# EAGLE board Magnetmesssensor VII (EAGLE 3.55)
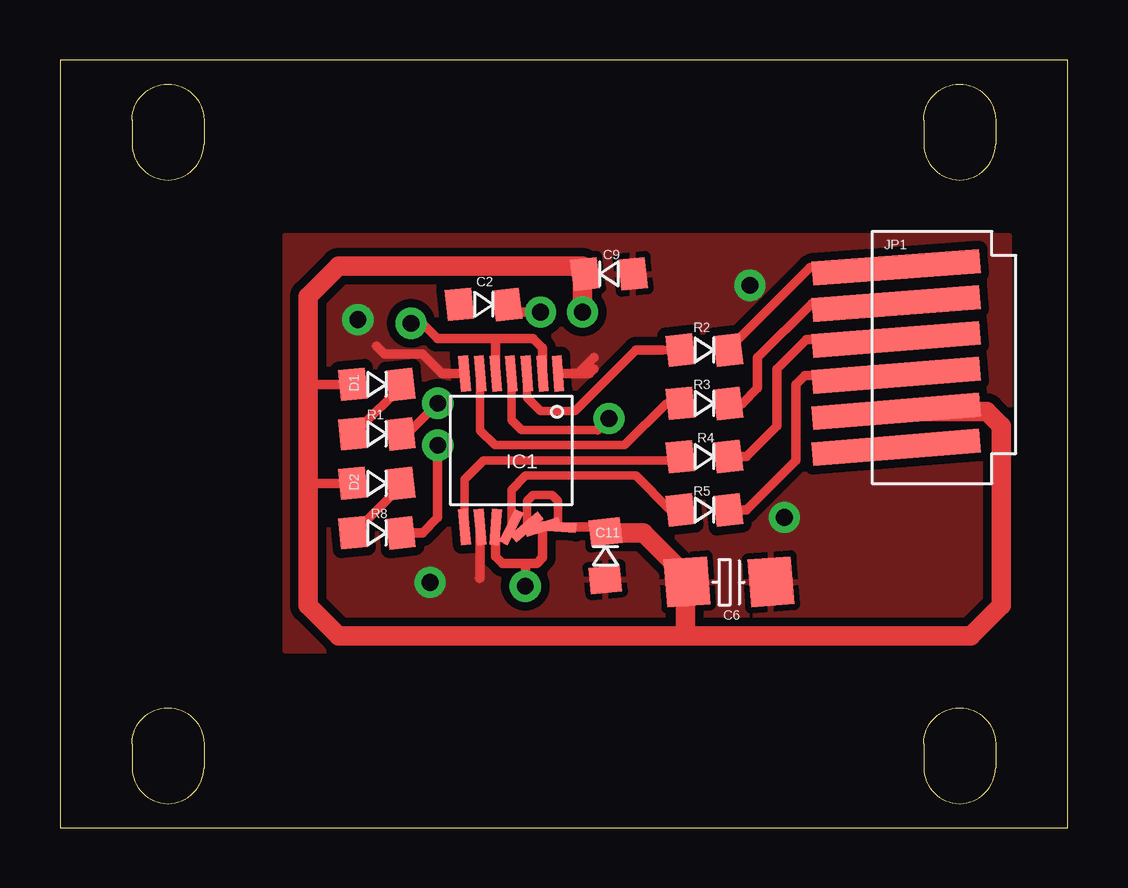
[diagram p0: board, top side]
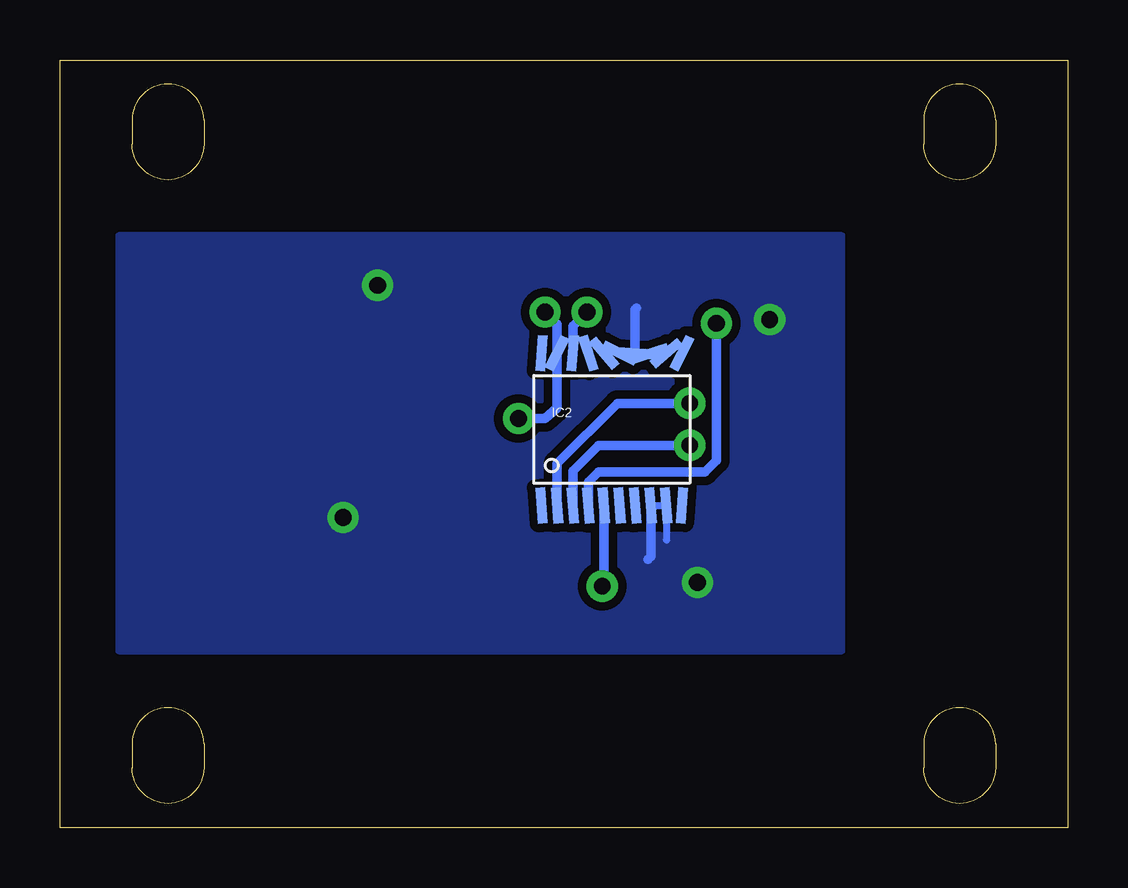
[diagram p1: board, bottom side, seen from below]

Size 42 x 32 mm. Coordinates in mm from the lower left corner, seen from the top.
Outline: 0,0 42,0 42,32 0,32 0,0
Outline: 3,29.5 3,28.5 arc180 6,28.5 6,29.5 arc180 3,29.5
Outline: 3,3.5 3,2.5 arc180 6,2.5 6,3.5 arc180 3,3.5
Outline: 36,3.5 36,2.5 arc180 39,2.5 39,3.5 arc180 36,3.5
Outline: 36,29.5 36,28.5 arc180 39,28.5 39,29.5 arc180 36,29.5
Copper layers used: Top, Bottom

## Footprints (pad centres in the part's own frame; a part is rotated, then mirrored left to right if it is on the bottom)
D0805 = smd 1.1 x 1.3 rotated 5.7:  -1,0 | smd 1.1 x 1.3 rotated 6.6:  1,0
D-ELKA = smd 1.8 x 2 rotated 4.4:  1.824,0.019 | smd 1.8 x 2 rotated 4.3:  -1.676,0.019
SOP14 = smd 0.4 x 1.5 rotated 4.6:  -0.05,-3.15 | smd 0.4 x 1.5 rotated 4.5:  -0.7,-3.15 | smd 0.4 x 1.5 rotated 4.4:  -1.35,-3.15 | smd 0.4 x 1.5 rotated 4.3:  -2,-3.15;  0.6,3.25 | smd 0.4 x 1.5 rotated 4.7:  0.6,-3.15;  1.25,-3.15 | smd 0.4 x 1.5 rotated 4.8:  1.9,-3.15 | smd 0.4 x 1.5 rotated 26.8:  -0.05,3.25 | smd 0.4 x 1.5 rotated 49.3:  -0.7,3.25 | smd 0.4 x 1.5 rotated 71.8:  -1.35,3.25 | smd 0.4 x 1.5 rotated 94.3:  -2,3.25 | smd 0.4 x 1.5 rotated 5:  1.25,3.25 | smd 0.4 x 1.5 rotated 4.9:  1.9,3.25
SOP20 = smd 0.4 x 1.5 rotated 4.3:  -2.925,-3.175;  2.925,-3.175 | smd 0.4 x 1.5 rotated 4.4:  -2.275,-3.175;  -2.925,3.175 | smd 0.4 x 1.5 rotated 4.5:  -1.625,-3.175 | smd 0.4 x 1.5 rotated 4.6:  -0.975,-3.175 | smd 0.4 x 1.5 rotated 4.7:  -0.325,-3.175;  0.325,-3.175 | smd 0.4 x 1.5 rotated 4.8:  0.975,-3.175 | smd 0.4 x 1.5 rotated 4.9:  1.625,-3.175 | smd 0.4 x 1.5 rotated 5:  2.275,-3.175 | smd 0.4 x 1.5 rotated 26.8:  2.925,3.175 | smd 0.4 x 1.5 rotated 49.3:  2.275,3.175 | smd 0.4 x 1.5 rotated 71.8:  1.625,3.175 | smd 0.4 x 1.5 rotated 94.3:  0.975,3.175 | smd 0.4 x 1.5 rotated 116.8:  0.325,3.175 | smd 0.4 x 1.5 rotated 139.3:  -0.325,3.175 | smd 0.4 x 1.5 rotated 161.8:  -0.975,3.175 | smd 0.4 x 1.5 rotated 184.3:  -1.625,3.175 | smd 0.4 x 1.5 rotated 206.8:  -2.275,3.175
L1,5X6 = smd 1 x 7 rotated 4.3:  -3.75,-1.25 | smd 1 x 7 rotated 4.4:  -2.25,-1.25 | smd 1 x 7 rotated 4.5:  -0.75,-1.25 | smd 1 x 7 rotated 4.6:  0.75,-1.25 | smd 1 x 7 rotated 4.7:  2.25,-1.25;  3.75,-1.25

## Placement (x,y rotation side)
C2  4,7æ  [D0805]  17.65,21.81 0 top
C6  10æ  [D-ELKA]  27.81,10.22 0 top
C9  100n  [D0805]  22.89,23.08 180 top
C11  100n  [D0805]  22.73,11.33 90 top
D1  Magnitude1  [D0805]  13.21,18.48 0 top
D2  Magnitude2  [D0805]  13.21,14.35 0 top
IC1  74HC86  [SOP14]  18.76,15.78 180 top
IC2  AS5311  [SOP20]  19,16.6 0 bottom
JP1  PINHD-1X6  [L1,5X6]  36.1,19.6 270 top
R1  1k  [D0805]  13.21,16.41 0 top
R2  56R  [D0805]  26.86,19.91 0 top
R3  56R  [D0805]  26.86,17.68 0 top
R4  56R  [D0805]  26.86,15.46 0 top
R5  56R  [D0805]  26.86,13.24 0 top
R8  1k  [D0805]  13.21,12.29 0 top

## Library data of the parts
C2 C6 C9 C11 D1 D2 IC1 JP1 R1-R5 R8 = CONTR1
IC2 = sensors

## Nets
+5V: C6. C9. C11. D1. D2. IC1. IC2. JP1.
A: IC1. IC2.
B: IC1. IC2.
GND: C2. C6. C9. C11. IC1. IC2. JP1.
MAGDECN: IC2. R8.
MAGINCN: IC2. R1.
N$1: IC1. R2.
N$2: D1. R1.
N$3: D2. R8.
N$5: IC1. R3.
N$6: IC1. R4.
N$7: IC1. R5.
N$8: JP1. R2.
N$10: JP1. R3.
N$11: JP1. R4.
N$12: JP1. R5.
N$16: C2. IC2.

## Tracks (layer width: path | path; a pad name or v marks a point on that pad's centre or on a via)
+5V  (via drill 0.7 pad 1.3)
  Top 0.35: 19.46,12.53 19.46,13.62 19.72,13.87 20.51,13.87 20.76,13.62 20.76,12.53 | 22.41,16.57 19.24,16.57 18.81,17 18.81,18.93
  Top 0.4: 12.21,18.48 10.35,18.48 10.35,18.64 | 10.35,14.35 12.21,14.35 | 10.35,14.35 | v21.78,21.49 C9. | v22.89,17.05 22.41,16.57 | 23.21,12.45 | C11. 23.21,12.45 | 20.76,12.53 23.12,12.53 23.21,12.45
  Top 0.813: v21.78,21.49 21.78,23.4 11.62,23.4 10.35,22.13 10.35,18.64 10.35,14.35 10.35,9.27 11.62,8 26.07,8 | 26.07,8 37.97,8 39.24,9.27 39.24,16.73 38.63,17.34 34.85,17.35 | C11. 23,12.33 22.73,12.29 24.32,12.29 26.14,10.47 C6. 26.14,10.15 26.23,10.06 26.07,10.06 26.07,8
  Bottom 0.4: v21.78,21.49 21.27,20.99 21.27,19.77 21.27,17.5 21.78,17.05 v22.89,17.05
A  (via drill 0.7 pad 1.3)
  Top 0.4: 18.16,18.93 18.16,20.26 18.13,20.38 | 18.13,20.38 19.72,20.38 20.11,19.98 20.11,18.93 | v14.64,21.02 15.11,21.02 15.75,20.38 17.34,20.38 17.49,20.38 18.13,20.38
  Bottom 0.4: 19.98,13.43 19.98,14.41 19.56,14.83 15.11,14.83 14.64,15.3 v14.64,21.02
B  (via drill 0.7 pad 1.3)
  Top 0.4: 18.16,12.53 18.16,11.3 18.45,11.02 19.4,11.02 | 20.11,12.53 20.11,11.26 19.88,11.02 19.4,11.02 | v19.4,10.06 19.4,11.02
  Bottom 0.4: 19.32,13.43 19.32,10.14 v19.4,10.06
GND  (via drill 0.7 pad 1.3)
  Top 0.4: 17.51,12.53 17.51,10.4 17.49,10.38 | 16.86,18.93 15.93,18.93 15.11,19.75 13.53,19.75 13.21,20.07 | 22.26,19.11 22.07,18.93 20.76,18.93 21.6,18.93 22.26,19.59
  Bottom 0.3: 17.38,13.43 17.2,13.43 17.18,13.4 17.15,13.43 16.73,13.43 16.73,11.99 16.7,11.97
  Bottom 0.4: 17.38,13.43 17.38,11.29 17.49,11.18 | 18.02,19.77 18.02,21.6 17.97,21.65
  other vias: 15.43,10.22 12.41,21.18 28.77,22.61 30.19,12.92
  pour Bottom (isolate 0.356): 9.4,7.37 9.4,24.67 39.56,24.67 39.56,7.37
  pour Top (isolate 0.356): 9.4,7.37 9.4,24.67 39.56,24.67 39.56,7.37
MAGDECN  (via drill 0.7 pad 1.3)
  Top 0.4: v15.75,15.94 15.75,12.92 15.11,12.29 R8.
  Bottom 0.4: 20.62,13.43 20.62,14.87 19.56,15.94 v15.75,15.94
MAGINCN  (via drill 0.7 pad 1.3)
  Top 0.4: R1. 14.48,16.41 v15.75,17.68
  Bottom 0.4: 21.27,13.43 21.27,15.17 18.76,17.68 v15.75,17.68
N$1
  Top 0.35: 19.46,18.93 19.46,17.94 20.03,17.37 21.46,17.37 24,19.91 25.86,19.91
  Top 0.4: 25.11,19.91 | 24,19.91 25.11,19.91
N$2
  Top 0.4: D1. 14.32,18.48 12.41,16.57 12.21,16.41
N$3
  Top 0.4: D2. 14.05,14.08 12.05,12.08 12.21,12.29
N$5
  Top 0.35: 17.51,18.93 17.51,16.55 18.13,15.94 23.53,15.94 25.27,17.68 25.86,17.68
N$6
  Top 0.35: 25.86,15.46 25.75,15.46 25.59,15.3 17.65,15.3 16.86,14.51 16.86,12.76
  Top 0.4: 16.86,12.76 IC1.
N$7
  Top 0.35: 18.81,12.53 18.81,14.08 19.4,14.67 24,14.67 25.43,13.24 | 25.43,13.24 | 25.43,13.24 25.86,13.24
N$8
  Top 0.4: R2. 27.86,19.95 31.26,23.35 34.85,23.35
N$10
  Top 0.4: 34.85,21.85 31.34,21.85 29.08,19.59 29.08,18.32 28.45,17.68 R3.
N$11
  Top 0.4: 34.85,20.35 31.11,20.35 29.88,19.11 29.88,16.73 28.61,15.46 R4.
N$12
  Top 0.4: 34.85,18.85 31.04,18.85 30.67,18.48 30.67,15.3 28.61,13.24 27.97,13.24 | 27.97,13.24 | R5. 27.97,13.24
N$16  (via drill 0.7 pad 1.3)
  Top 0.4: 18.29,21.49 | C2. 18.29,21.49 | 18.29,21.49 v20.03,21.49
  Bottom 0.4: 20.62,19.77 20.62,20.9 v20.03,21.49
